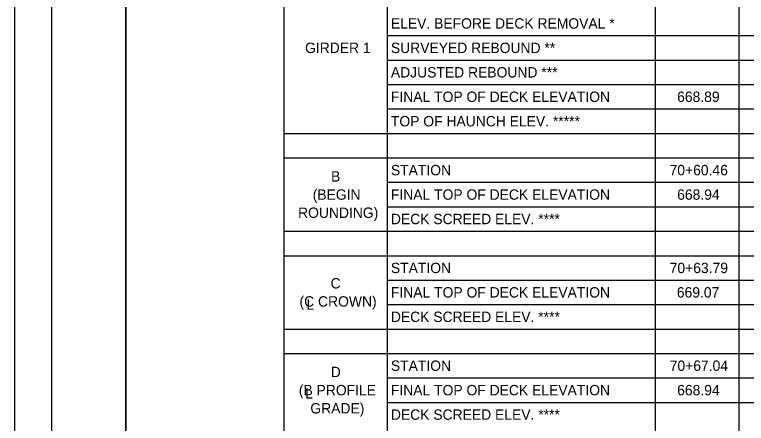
# Model space of a CAD drawing. Extents: x 0 to 34, y 0 to 22.
# Drawn here: x 0 to 9.87, y 11.03 to 16.55 of the extents above; entities that cross this region are included whole.
import ezdxf

# ---------------------------------------------------------------- set-up
doc = ezdxf.new("R2010")
doc.units = 0
for name, color, linetype in [('SH_Border', 7, 'Continuous'), ('SH_Cut_Line', 7, 'Continuous'), ('SH_Text', 7, 'Continuous')]:
    doc.layers.add(name, color=color, linetype=linetype)

msp = doc.modelspace()

# ---------------------------------------------------------------- linework, layer by layer
at = {"layer": 'SH_Border'}
for points in [[(0.5, 21.5), (1.5, 21.5), (1.5, 0.5), (0.5, 0.5)], [(1.5, 21.5), (33.5, 21.5), (33.5, 0.5), (1.5, 0.5)]]:
    msp.add_lwpolyline(points, close=True, dxfattribs=at)
at = {"layer": 'SH_Cut_Line'}
msp.add_lwpolyline([(0, 0), (34, 0), (34, 22), (0, 22)], close=True, dxfattribs=at)
at = {"layer": 'SH_Text'}
for p, q in [((3.6273, 20.5877), (3.6273, 1.7561)), ((5.0222, 20.0804), (5.0222, 1.7561)), ((8.6364, 20.0804), (8.6364, 1.7561)), ((9.765, 19.4083), (9.765, 1.7561)), ((5.0222, 16.2634), (20.0494, 16.2634)), ((5.0222, 15.9337), (20.0494, 15.9337)), ((5.0222, 15.604), (20.0494, 15.604)), ((5.0222, 15.2743), (20.0494, 15.2743)), ((3.6273, 14.9445), (20.0494, 14.9445)), ((3.6273, 14.6148), (20.0494, 14.6148)), ((5.0222, 14.2851), (20.0494, 14.2851)), ((5.0222, 13.9554), (20.0494, 13.9554)), ((3.6273, 13.6257), (20.0494, 13.6257)), ((3.6273, 13.296), (20.0494, 13.296)), ((5.0222, 12.9663), (20.0494, 12.9663)), ((5.0222, 12.6366), (20.0494, 12.6366)), ((3.6273, 12.3069), (20.0494, 12.3069)), ((3.6273, 11.9772), (20.0494, 11.9772)), ((5.0222, 11.6474), (20.0494, 11.6474)), ((5.0222, 11.3177), (20.0494, 11.3177))]:
    msp.add_line(p, q, dxfattribs=at)

# ---------------------------------------------------------------- texts
for s, p in [('ELEV. BEFORE DECK REMOVAL *', (5.0729, 16.3582)), ('GIRDER 1', (3.9158, 16.0285)), ('SURVEYED REBOUND **', (5.0729, 16.0285)), ('ADJUSTED REBOUND ***', (5.0729, 15.6988)), ('FINAL TOP OF DECK ELEVATION', (5.0729, 15.3691)), ('668.89', (8.932, 15.3691)), ('TOP OF HAUNCH ELEV. *****', (5.0729, 15.0394)), ('STATION', (5.0729, 14.38)), ('70+60.46', (8.8303, 14.38)), ('B                                ', (4.2659, 14.2953)), ('(BEGIN ', (4.0188, 14.0503)), ('FINAL TOP OF DECK ELEVATION', (5.0729, 14.0503)), ('668.94', (8.9326, 14.0503)), ('ROUNDING)', (3.8213, 13.8053)), ('DECK SCREED ELEV. ****', (5.0729, 13.7206)), ('STATION', (5.0729, 13.0611)), ('70+63.79', (8.8317, 13.0611)), ('C                              ', (4.2604, 12.8539)), ('FINAL TOP OF DECK ELEVATION', (5.0729, 12.7314)), ('669.07', (8.9281, 12.7314)), ('(C CROWN)', (3.841, 12.6089)), ('L', (3.9352, 12.5664)), ('DECK SCREED ELEV. ****', (5.0729, 12.4017)), ('STATION', (5.0729, 11.7423)), ('70+67.04', (8.8323, 11.7423)), ('D                                     ', (4.2621, 11.6576)), ('(B PROFILE ', (3.8317, 11.4126)), ('FINAL TOP OF DECK ELEVATION', (5.0729, 11.4126)), ('668.94', (8.9326, 11.4126)), ('L', (3.9161, 11.3697)), ('GRADE)', (3.9875, 11.1676)), ('DECK SCREED ELEV. ****', (5.0729, 11.0829))]:
    msp.add_text(s, height=0.14, dxfattribs=at).set_placement(p)

doc.saveas('drawing.dxf')
